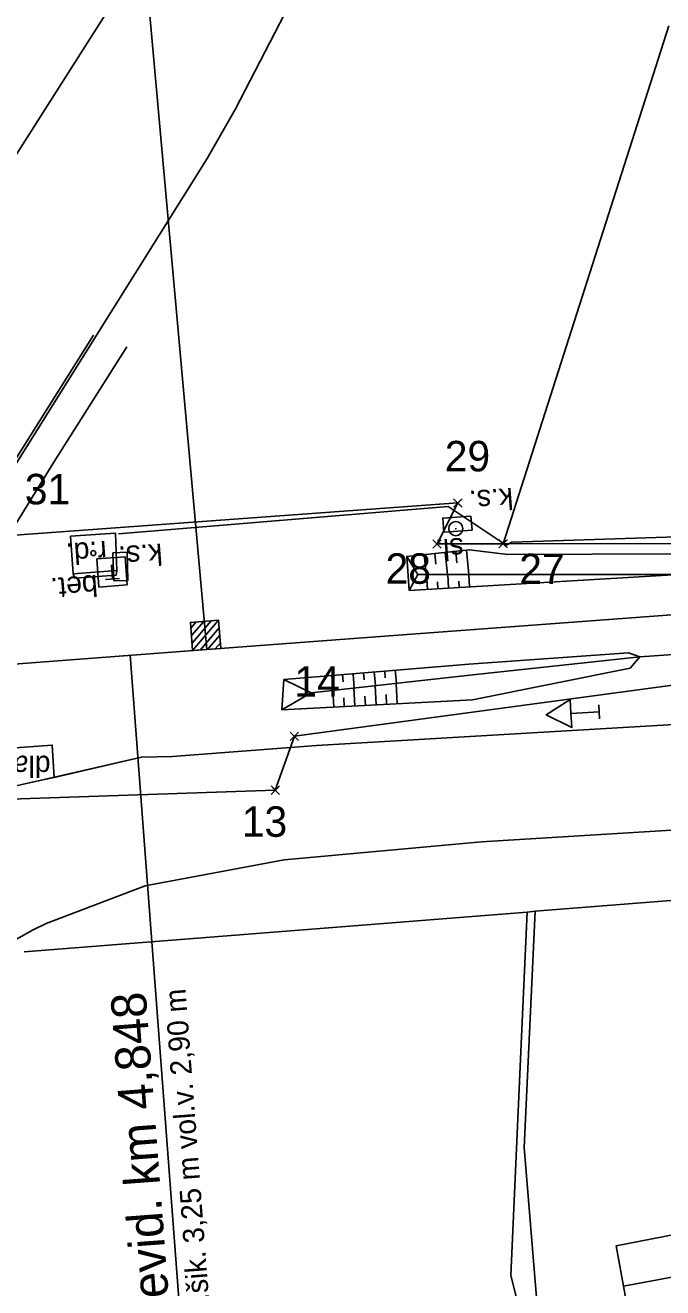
# Model space of a CAD drawing. Extents: x -779302 to -774398, y -1144902 to -1142831.
# Drawn here: x -775066.8 to -775021.7, y -1144493.5 to -1144404.1 of the extents above; entities that cross this region are included whole.
import ezdxf

# ---------------------------------------------------------------- set-up
doc = ezdxf.new("R2010")
doc.units = 0
for name, color, linetype in [('Hranice parcel', 7, 'Continuous'), ('legenda I_5_2 - Vrstva 53', 7, 'Continuous'), ('SŽDC', 7, 'Continuous'), ('Vnitřní kresba', 7, 'Continuous'), ('zjednodus_g_situ-seda - Vrstva 1', 7, 'Continuous'), ('zjednodus_g_situ-seda - Vrstva 13', 7, 'Continuous'), ('zjednodus_g_situ-seda - Vrstva 16', 7, 'Continuous'), ('zjednodus_g_situ-seda - Vrstva 17', 7, 'Continuous'), ('zjednodus_g_situ-seda - Vrstva 18', 7, 'Continuous'), ('zjednodus_g_situ-seda - Vrstva 23', 7, 'Continuous'), ('zjednodus_g_situ-seda - Vrstva 25', 7, 'Continuous'), ('zjednodus_g_situ-seda - Vrstva 3', 7, 'Continuous'), ('zjednodus_g_situ-seda - Vrstva 33', 7, 'Continuous'), ('zjednodus_g_situ-seda - Vrstva 48', 7, 'Continuous'), ('zjednodus_g_situ-seda - Vrstva 49', 7, 'Continuous'), ('zjednodus_g_situ-seda - Vrstva 50', 7, 'Continuous'), ('zjednodus_g_situ-seda - Vrstva 51', 7, 'Continuous'), ('zjednodus_g_situ-seda - Vrstva 59', 7, 'Continuous')]:
    doc.layers.add(name, color=color, linetype=linetype)

msp = doc.modelspace()

# ---------------------------------------------------------------- linework, layer by layer
at = {"layer": 'Hranice parcel'}
for p, q in [((-775032.95, -1144440.83), (-775021.23, -1144404.14)), ((-775066.86, -1144469.73), (-775031.24, -1144466.92)), ((-775031.24, -1144466.92), (-775030.68, -1144466.87))]:
    msp.add_line(p, q, dxfattribs=at)
for points in [[(-774980.54, -1144260.84), (-774999.66, -1144289.45), (-775012.69, -1144325.05), (-775026.23, -1144360.34), (-775051.92, -1144410.08), (-775053.91, -1144413.55), (-775071.04, -1144440.88)], [(-775070.46, -1144418.03), (-775061.58, -1144404.07), (-775053.67, -1144391.64)], [(-774832.04, -1144435.58), (-774869.06, -1144438.3), (-774919.16, -1144442.27), (-774942.23, -1144444.12), (-775006.07, -1144448.84), (-775047.73, -1144454.47), (-775049.08, -1144458.29), (-775076.86, -1144459.23)], [(-775071.04, -1144440.88), (-775069.78, -1144440.38), (-775036.16, -1144437.94), (-775037.63, -1144440.85), (-775032.95, -1144440.83)], [(-775032.95, -1144440.83), (-775006.9, -1144440.82), (-775003.31, -1144440.57)], [(-775030.68, -1144466.87), (-774981.78, -1144463.01), (-774977.53, -1144462.71)], [(-775031.24, -1144466.92), (-775031.6, -1144474.7), (-775032.41, -1144492.66), (-775025.96, -1144518.08), (-775023.75, -1144523.35), (-775022.07, -1144523.02)], [(-775030.68, -1144466.87), (-775031.45, -1144483.59), (-775030.29, -1144497.96), (-775026.8, -1144497.32), (-775022.07, -1144523.02)], [(-774972.85, -1144500.27), (-774974.21, -1144492.89), (-774978.42, -1144493.64), (-774980.01, -1144485.11), (-774981.79, -1144485.44), (-774982.01, -1144484.24), (-774984.54, -1144484.75), (-774984.32, -1144485.92), (-775014.34, -1144491.54), (-775014.88, -1144488.6), (-775024.95, -1144490.57), (-775024.42, -1144493.43), (-775019.94, -1144517.62)]]:
    msp.add_lwpolyline(points, dxfattribs=at)
at = {"layer": 'legenda I_5_2 - Vrstva 53'}
for points in [[(-775474.88, -1144449.28), (-775426.17, -1144455.72), (-775417.93, -1144456.81), (-775377.95, -1144459.1), (-775351.35, -1144460.68), (-775341.64, -1144460.83), (-775337.71, -1144460.89), (-775301.48, -1144461.27), (-775254.16, -1144459.9), (-775170.99, -1144453.66), (-775138.01, -1144449.91), (-775088.39, -1144447.82), (-775071.04, -1144440.88), (-775069.78, -1144440.38), (-775036.16, -1144437.94), (-775037.63, -1144440.85), (-775032.95, -1144440.83), (-775006.9, -1144440.82), (-775003.31, -1144440.57), (-774957.77, -1144437.47), (-774890.46, -1144432.61)], [(-774919.16, -1144442.27), (-774942.23, -1144444.12), (-775006.07, -1144448.84), (-775047.73, -1144454.47), (-775049.08, -1144458.29), (-775076.86, -1144459.23), (-775096.64, -1144457.51), (-775137.35, -1144459.01), (-775201.24, -1144463.92), (-775204.62, -1144464.16), (-775217.76, -1144465.11), (-775237.91, -1144466.56), (-775289.7, -1144468.96), (-775332.79, -1144469.99)]]:
    msp.add_lwpolyline(points, dxfattribs=at)
at = {"layer": 'SŽDC'}
for p, q in [((-775035.96, -1144438.14), (-775036.46, -1144437.64)), ((-775035.96, -1144437.74), (-775036.46, -1144438.24)), ((-775036.36, -1144438.14), (-775035.86, -1144437.64)), ((-775036.36, -1144437.74), (-775035.86, -1144438.24)), ((-775036.16, -1144437.94), (-775036.16, -1144437.94)), ((-775037.43, -1144441.05), (-775037.93, -1144440.55)), ((-775037.43, -1144440.65), (-775037.93, -1144441.15)), ((-775037.83, -1144441.05), (-775037.33, -1144440.55)), ((-775037.83, -1144440.65), (-775037.33, -1144441.15)), ((-775037.63, -1144440.85), (-775037.63, -1144440.85)), ((-775032.75, -1144441.03), (-775033.25, -1144440.53)), ((-775032.75, -1144440.63), (-775033.25, -1144441.13)), ((-775033.15, -1144441.03), (-775032.65, -1144440.53)), ((-775033.15, -1144440.63), (-775032.65, -1144441.13)), ((-775032.95, -1144440.83), (-775032.95, -1144440.83)), ((-775047.53, -1144454.67), (-775048.03, -1144454.17)), ((-775047.53, -1144454.27), (-775048.03, -1144454.77)), ((-775047.93, -1144454.67), (-775047.43, -1144454.17)), ((-775047.93, -1144454.27), (-775047.43, -1144454.77)), ((-775047.73, -1144454.47), (-775047.73, -1144454.47)), ((-775048.88, -1144458.49), (-775049.38, -1144457.99)), ((-775049.28, -1144458.49), (-775048.78, -1144457.99)), ((-775048.88, -1144458.09), (-775049.38, -1144458.59)), ((-775049.28, -1144458.09), (-775048.78, -1144458.59)), ((-775049.08, -1144458.29), (-775049.08, -1144458.29))]:
    msp.add_line(p, q, dxfattribs=at)
for points in [[(-775474.88, -1144449.28), (-775426.17, -1144455.72), (-775417.93, -1144456.81), (-775377.95, -1144459.1), (-775351.35, -1144460.68), (-775341.64, -1144460.83), (-775337.71, -1144460.89), (-775301.48, -1144461.27), (-775254.16, -1144459.9), (-775170.99, -1144453.66), (-775138.01, -1144449.91), (-775088.39, -1144447.82), (-775071.04, -1144440.88), (-775069.78, -1144440.38), (-775036.16, -1144437.94), (-775037.63, -1144440.85), (-775032.95, -1144440.83), (-775006.9, -1144440.82), (-775003.31, -1144440.57), (-774957.77, -1144437.47), (-774890.46, -1144432.61)], [(-774919.16, -1144442.27), (-774942.23, -1144444.12), (-775006.07, -1144448.84), (-775047.73, -1144454.47), (-775049.08, -1144458.29), (-775076.86, -1144459.23), (-775096.64, -1144457.51), (-775137.35, -1144459.01), (-775201.24, -1144463.92), (-775204.62, -1144464.16), (-775217.76, -1144465.11), (-775237.91, -1144466.56), (-775289.7, -1144468.96), (-775332.79, -1144469.99)]]:
    msp.add_lwpolyline(points, dxfattribs=at)
at = {"layer": 'Vnitřní kresba'}
msp.add_line((-775024.42, -1144493.43), (-775014.34, -1144491.54), dxfattribs=at)
at = {"layer": 'zjednodus_g_situ-seda - Vrstva 1'}
msp.add_lwpolyline([(-774830.163, -1144431.482), (-774850.563, -1144433.022), (-774864.475, -1144434.064), (-774869.912, -1144434.473), (-774871.827, -1144434.617), (-774885.853, -1144435.682), (-774900.88, -1144436.804), (-774924.49, -1144438.587), (-774948.039, -1144440.364), (-774972.389, -1144442.197), (-774996.531, -1144444.018), (-775020.057, -1144445.789), (-775040.384, -1144447.314), (-775053.937, -1144448.326), (-775072.564, -1144449.732), (-775089.145, -1144450.956), (-775106.822, -1144452.299), (-775129.866, -1144454.038), (-775154.332, -1144455.872), (-775163.87, -1144456.589), (-775186.746, -1144458.314), (-775211.372, -1144460.168), (-775237.518, -1144462.13)], dxfattribs=at)
at = {"layer": 'zjednodus_g_situ-seda - Vrstva 13'}
msp.add_lwpolyline([(-774871.7, -1144437.646), (-774885.67, -1144438.638), (-774900.901, -1144439.759), (-774924.226, -1144441.559), (-774947.713, -1144443.292), (-774972.002, -1144445.163), (-774996.171, -1144446.963), (-775023.261, -1144448.853)], dxfattribs=at)
at = {"layer": 'zjednodus_g_situ-seda - Vrstva 16'}
msp.add_lwpolyline([(-775063.399, -1144442.957), (-775060.306, -1144442.717), (-775060.349, -1144443.056), (-775063.294, -1144443.277), (-775063.399, -1144442.957)], dxfattribs=at)
at = {"layer": 'zjednodus_g_situ-seda - Vrstva 17'}
msp.add_lwpolyline([(-774872.154, -1144430.412), (-774885.89, -1144432.054), (-774902.942, -1144433.126), (-774924.674, -1144434.792), (-774949.136, -1144436.402), (-774972.464, -1144437.97), (-774996.34, -1144439.603), (-775002.854, -1144440.114), (-775020.655, -1144440.349), (-775032.337, -1144440.732), (-775032.737, -1144440.939), (-775036.851, -1144438.197), (-775060.184, -1144440.14)], dxfattribs=at)
at = {"layer": 'zjednodus_g_situ-seda - Vrstva 18'}
msp.add_line((-775054.758, -1144509.562), (-775059.35, -1144448.735), dxfattribs=at)
at = {"layer": 'zjednodus_g_situ-seda - Vrstva 23'}
msp.add_lwpolyline([(-775063.59, -1144440.301), (-775063.399, -1144442.957), (-775060.306, -1144442.717), (-775060.404, -1144440.08), (-775063.59, -1144440.301)], dxfattribs=at)
at = {"layer": 'zjednodus_g_situ-seda - Vrstva 25'}
for points in [[(-775035.227, -1144438.872), (-775035.152, -1144439.869), (-775037.147, -1144440.018), (-775037.222, -1144439.021), (-775035.227, -1144438.872)], [(-775060.576, -1144441.467), (-775059.577, -1144441.434), (-775059.512, -1144443.433), (-775060.511, -1144443.466), (-775060.576, -1144441.467)]]:
    msp.add_lwpolyline(points, dxfattribs=at)
at = {"layer": 'zjednodus_g_situ-seda - Vrstva 3'}
for p, q in [((-775053.937, -1144448.326), (-775059.515, -1144386.22)), ((-775054.677, -1144446.376), (-775055.054, -1144446.815)), ((-775054.148, -1144446.336), (-775055.014, -1144447.343)), ((-775053.619, -1144446.296), (-775054.974, -1144447.873)), ((-775053.09, -1144446.256), (-775054.934, -1144448.401)), ((-775053.05, -1144446.785), (-775054.406, -1144448.361)), ((-775053.011, -1144447.314), (-775053.876, -1144448.321)), ((-775052.971, -1144447.843), (-775053.348, -1144448.282))]:
    msp.add_line(p, q, dxfattribs=at)
msp.add_lwpolyline([(-775052.94, -1144448.251), (-775054.934, -1144448.401), (-775055.085, -1144446.407), (-775053.09, -1144446.256)], close=True, dxfattribs=at)
at = {"layer": 'zjednodus_g_situ-seda - Vrstva 33'}
for p, q in [((-775060.604, -1144443.331), (-775060.68, -1144442.333)), ((-775060.106, -1144443.293), (-775061.103, -1144443.368))]:
    msp.add_line(p, q, dxfattribs=at)
msp.add_lwpolyline([(-775059.57, -1144443.754), (-775061.564, -1144443.904), (-775061.714, -1144441.91), (-775059.72, -1144441.76), (-775059.57, -1144443.754)], dxfattribs=at)
at = {"layer": 'zjednodus_g_situ-seda - Vrstva 48'}
for p, q in [((-775038.538, -1144441.6), (-775038.394, -1144443.018)), ((-775037.792, -1144441.524), (-775037.716, -1144442.271)), ((-775037.046, -1144441.448), (-775036.886, -1144443.019)), ((-775036.3, -1144441.372), (-775036.216, -1144442.196)), ((-775035.554, -1144441.297), (-775035.379, -1144443.019)), ((-775038.315, -1144444.073), (-775038.378, -1144443.018)), ((-775037.567, -1144444.029), (-775037.596, -1144443.524)), ((-775036.818, -1144443.985), (-775036.875, -1144443.019)), ((-775036.069, -1144443.94), (-775036.096, -1144443.48)), ((-775035.32, -1144443.896), (-775035.372, -1144443.019)), ((-775042.824, -1144449.979), (-775042.783, -1144450.474)), ((-775042.077, -1144449.917), (-775041.996, -1144450.886)), ((-775041.33, -1144449.854), (-775041.29, -1144450.328)), ((-775040.582, -1144449.792), (-775040.505, -1144450.718)), ((-775045.066, -1144450.167), (-775044.978, -1144451.221)), ((-775044.319, -1144450.104), (-775044.276, -1144450.621)), ((-775043.572, -1144450.042), (-775043.487, -1144451.053)), ((-775041.948, -1144452.244), (-775042.02, -1144450.888)), ((-775040.45, -1144452.165), (-775040.526, -1144450.72)), ((-775044.944, -1144452.402), (-775045.006, -1144451.224)), ((-775044.195, -1144452.363), (-775044.227, -1144451.751)), ((-775043.446, -1144452.323), (-775043.513, -1144451.056)), ((-775042.697, -1144452.284), (-775042.732, -1144451.628)), ((-775041.199, -1144452.205), (-775041.236, -1144451.505))]:
    msp.add_line(p, q, dxfattribs=at)
at = {"layer": 'zjednodus_g_situ-seda - Vrstva 49'}
for p, q in [((-775038.997, -1144443.018), (-775039.769, -1144441.725)), ((-775039.602, -1144444.149), (-775038.997, -1144443.018)), ((-775039.602, -1144444.149), (-775020.538, -1144443.023)), ((-775046.551, -1144451.398), (-775048.619, -1144452.596))]:
    msp.add_line(p, q, dxfattribs=at)
for points in [[(-774902.942, -1144433.126), (-774924.674, -1144434.792), (-774949.136, -1144436.402), (-774972.464, -1144437.97), (-774996.898, -1144440.491), (-775020.67, -1144441.549), (-775032.618, -1144441.599), (-775035.332, -1144441.274), (-775039.769, -1144441.725), (-775039.602, -1144444.149)], [(-774902.942, -1144433.126), (-774902.91, -1144434.561), (-774924.499, -1144436.114), (-774948.641, -1144437.835), (-774972.468, -1144439.524), (-774996.85, -1144441.35), (-775020.538, -1144443.023), (-775038.997, -1144443.018)], [(-775023.261, -1144448.853), (-775024.064, -1144448.57), (-775035.38, -1144449.357), (-775048.467, -1144450.451), (-775048.619, -1144452.596)], [(-775023.261, -1144448.853), (-775023.964, -1144449.645), (-775035.12, -1144451.884), (-775048.619, -1144452.596)], [(-775023.261, -1144448.853), (-775035.089, -1144450.109), (-775046.551, -1144451.398), (-775048.467, -1144450.451)]]:
    msp.add_lwpolyline(points, dxfattribs=at)
at = {"layer": 'zjednodus_g_situ-seda - Vrstva 50'}
msp.add_line((-775036.252, -1144439.758), (-775036.352, -1144439.766), dxfattribs=at)
msp.add_circle((-775036.302, -1144439.762), 0.5, dxfattribs=at)
at = {"layer": 'zjednodus_g_situ-seda - Vrstva 51'}
msp.add_line((-775026.121, -1144453.244), (-775026.175, -1144452.246), dxfattribs=at)
for points in [[(-775072.615, -1144443.016), (-775067.053, -1144434.186), (-775061.956, -1144426.058)], [(-775059.582, -1144426.886), (-775064.766, -1144435.047), (-775070.561, -1144444.451)], [(-775066.391, -1144457.75), (-775069.344, -1144458.416), (-775070.389, -1144458.562), (-775072.358, -1144458.461), (-775074.332, -1144457.804), (-775076.464, -1144455.753), (-775077.15, -1144453.872), (-775077.344, -1144451.714)], [(-775073.156, -1144451.284), (-775071.098, -1144455.544), (-775064.872, -1144455.092), (-775064.737, -1144457.385)], [(-775004.347, -1144452.658), (-775046.153, -1144455.13), (-775056.354, -1144455.898), (-775058.554, -1144455.942), (-775064.737, -1144457.385), (-775065.417, -1144457.526), (-775066.391, -1144457.75)], [(-775026.148, -1144452.745), (-775028.145, -1144452.855), (-775028.2, -1144451.856), (-775029.892, -1144452.951), (-775028.09, -1144453.853), (-775028.145, -1144452.855)], [(-775056.354, -1144455.898), (-775058.555, -1144455.943), (-775065.435, -1144457.525), (-775066.391, -1144457.75)], [(-775014.5, -1144460.713), (-775034.488, -1144461.945), (-775048.445, -1144463.235), (-775058.296, -1144465.059), (-775065.294, -1144467.733), (-775066.217, -1144468.171)], [(-775014.5, -1144460.713), (-775034.486, -1144461.946), (-775048.463, -1144463.23), (-775058.29, -1144465.062), (-775065.295, -1144467.724), (-775066.217, -1144468.171)], [(-775066.217, -1144468.171), (-775069.289, -1144469.885), (-775070.118, -1144470.442), (-775075.959, -1144474.293), (-775079.593, -1144477.753), (-775082.412, -1144481.914)]]:
    msp.add_lwpolyline(points, dxfattribs=at)
at = {"layer": 'zjednodus_g_situ-seda - Vrstva 59'}
msp.add_circle((-775061.961, -1144441.495), 0.175, dxfattribs=at)

# ---------------------------------------------------------------- texts
at = {"layer": 'SŽDC'}
for s, p in [('29', (-775037.082, -1144435.707)), ('31', (-775066.814, -1144438.043)), ('28', (-775041.274, -1144443.669)), ('27', (-775031.808, -1144443.693)), ('14', (-775047.73, -1144451.665)), ('13', (-775051.451, -1144461.592))]:
    msp.add_text(s, height=2.16, dxfattribs=at).set_placement(p)
at = {"layer": 'zjednodus_g_situ-seda - Vrstva 16'}
msp.add_text('bet.', height=1.5, rotation=184.29157, dxfattribs=at).set_placement((-775061.705, -1144443.022))
at = {"layer": 'zjednodus_g_situ-seda - Vrstva 18'}
for s, height, p in [('evid. km 4,848', 2.5, (-775056.627, -1144494.188)), ('sv.kol. 3,00 m sv.šik. 3,25 m vol.v. 2,90 m', 1.5, (-775052.644, -1144509.324))]:
    msp.add_text(s, height=height, rotation=94.3166, dxfattribs=at).set_placement(p)
at = {"layer": 'zjednodus_g_situ-seda - Vrstva 23'}
msp.add_text('r.d.', height=1.5, rotation=183.96802, dxfattribs=at).set_placement((-775061.054, -1144440.617))
at = {"layer": 'zjednodus_g_situ-seda - Vrstva 25'}
for rotation, p in [(184.29048, (-775032.289, -1144436.862)), (184.13207, (-775057.116, -1144440.808))]:
    msp.add_text('k.s.', height=1.5, rotation=rotation, dxfattribs=at).set_placement(p)
at = {"layer": 'zjednodus_g_situ-seda - Vrstva 50'}
msp.add_text('sl.', height=1.5, rotation=184.29048, dxfattribs=at).set_placement((-775035.794, -1144440.403))
at = {"layer": 'zjednodus_g_situ-seda - Vrstva 51'}
msp.add_text('dlaž.', height=1.5, rotation=180.02336, dxfattribs=at).set_placement((-775064.993, -1144455.846))

doc.saveas('drawing.dxf')
